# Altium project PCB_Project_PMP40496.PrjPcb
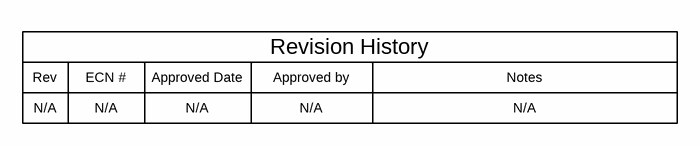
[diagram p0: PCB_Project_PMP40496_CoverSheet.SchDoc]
TID: N/A; TechSupport: http://www.ti.com/support; SCH_Rev: E1; PRJ_Title: 2-cell USB Boost Charger with OTG Reference Design; PRJ_Number: PMP40496; PRJ_Engineer: San Chen; PRJ_Customer: Public Release; PCB_Rev: E1; PCB_Layout: San Chen; CopyrightYear: 2018
4 sheets, 186 parts. Net scope: global (net labels, ports and power ports of the same name join across sheets).
Board file: PCB_Project_PMP40496_PCB.PcbDoc
Sheets:
  PCB_Project_PMP40496_CoverSheet.SchDoc
  PCB_Project_PMP40496_BatteryPack.SchDoc
  PCB_Project_PMP40496_BatteryCharge.SchDoc
  PCB_Project_PMP40496_Control.SchDoc

## Sheet PCB_Project_PMP40496_CoverSheet.SchDoc: Block Diagram
size 431 x 279 mm; Date: Not shown in title block; ApprovedBy: Not shown in title block; CheckedBy: Not shown in title block; Author: Not shown in title block; CompanyName: Not shown in title block; DrawnBy: San Chen; Engineer: Not shown in title block; Organization: Not shown in title block; Address1: Not shown in title block; Address2: Not shown in title block; Address3: Not shown in title block; Address4: Not shown in title block; DocumentNumber: 1; Revision: Use project parameter SCH_Rev; SheetNumber: 1; SheetTotal: 4; PageSetup: Record=PageOptions¦CenterHorizontal=True¦CenterVertical=True¦PrintScale=1.00¦XCorrection=1.00¦YCorrection=1.00¦PrintKind=0¦BorderSize=5000000¦LeftOffset=0¦BottomOffset=0¦Orientation=2¦PaperLength=1000¦PaperWidth=1000¦Scale=100¦PaperSource=15¦PrintQuality=600¦MediaType=1¦DitherType=10¦PaperKind=Letter¦PrintScaleMode=1

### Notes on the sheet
- Rev
- N/A
- ECN #
- Approved Date
- Approved by
- Revision History
- Notes

## Sheet PCB_Project_PMP40496_BatteryPack.SchDoc: Battery Pack
size 431 x 279 mm; Date: Not shown in title block; ApprovedBy: Not shown in title block; CheckedBy: Not shown in title block; Author: Not shown in title block; CompanyName: Not shown in title block; DrawnBy: San Chen; Engineer: Not shown in title block; Organization: Not shown in title block; Address1: Not shown in title block; Address2: Not shown in title block; Address3: Not shown in title block; Address4: Not shown in title block; DocumentNumber: 1; Revision: Use project parameter SCH_Rev; SheetNumber: 4; SheetTotal: 4; PageSetup: Record=PageOptions¦CenterHorizontal=True¦CenterVertical=True¦PrintScale=1.00¦XCorrection=1.00¦YCorrection=1.00¦PrintKind=0¦BorderSize=5000000¦LeftOffset=0¦BottomOffset=0¦Orientation=2¦PaperLength=1000¦PaperWidth=1000¦Scale=100¦PaperSource=15¦PrintQuality=600¦MediaType=1¦DitherType=10¦PaperKind=Letter¦PrintScaleMode=1
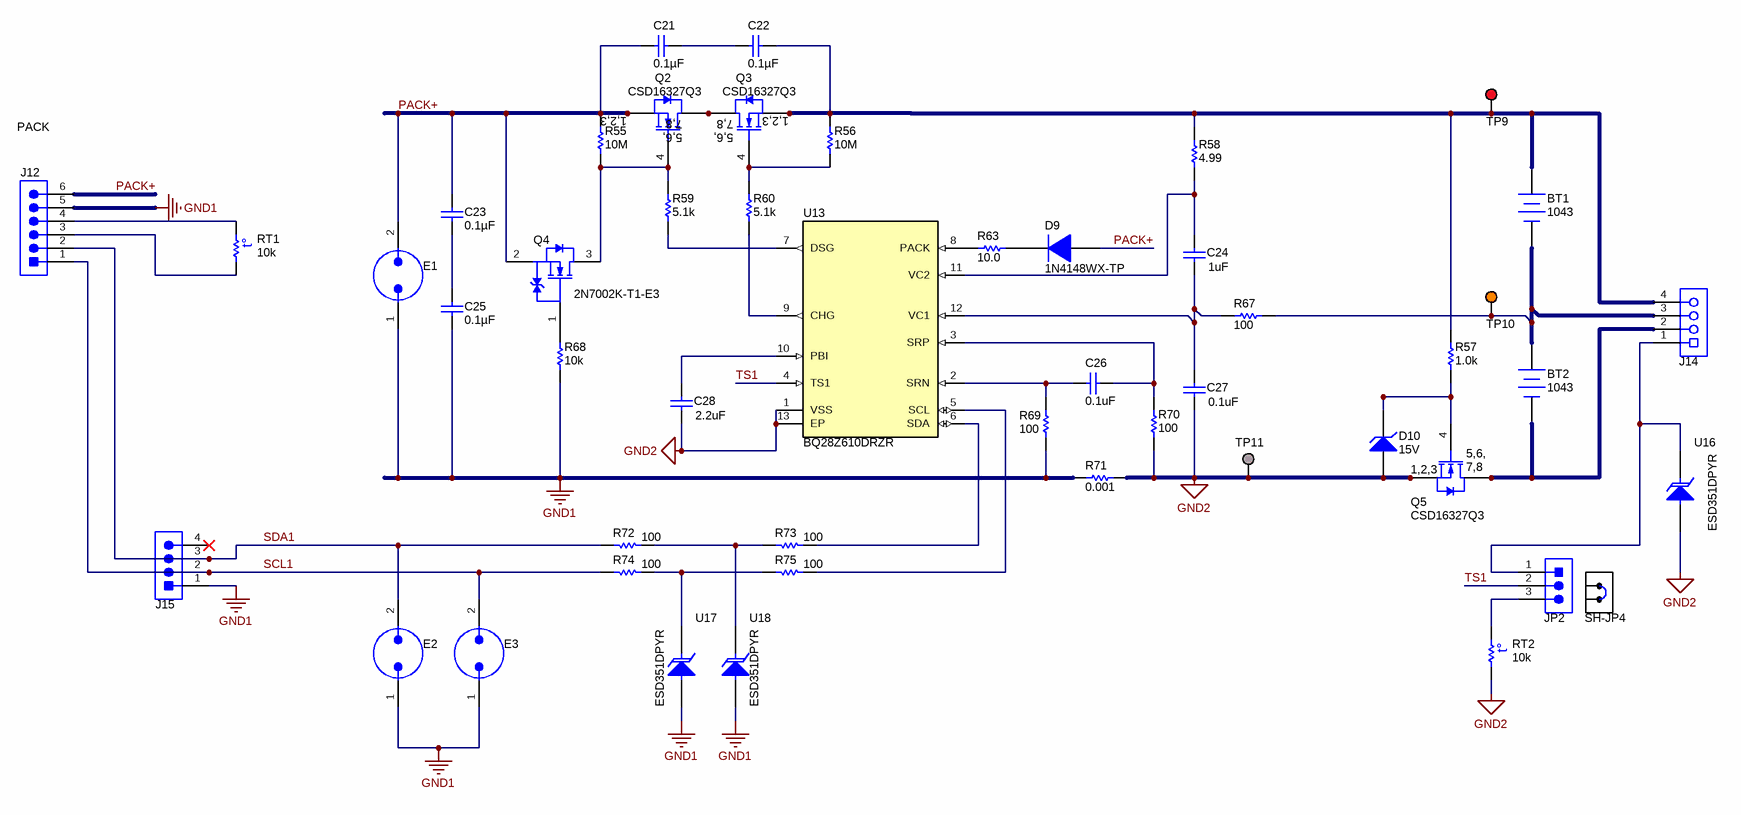
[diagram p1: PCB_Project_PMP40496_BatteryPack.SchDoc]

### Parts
BT1  1043  [BAT_1043]
BT2  1043  [BAT_1043]
C21  ValueDisplayed: 0.1µF  [0402]  (hidden comment: C1005X7R1H104K050BB)
C22  ValueDisplayed: 0.1µF  [0402]  (hidden comment: C1005X7R1H104K050BB)
C23  ValueDisplayed: 0.1µF  [0402]  (hidden comment: C1005X7R1H104K050BB)
C24  ValueDisplayed: 1uF  [0402]  (hidden comment: EMK105BJ105KVHF)
C25  ValueDisplayed: 0.1µF  [0402]  (hidden comment: C1005X7R1H104K050BB)
C26  ValueDisplayed: 0.1uF  [0402]  (hidden comment: GRM155R71E104KE14D)
C27  ValueDisplayed: 0.1uF  [0402]  (hidden comment: GRM155R71E104KE14D)
C28  ValueDisplayed: 2.2uF  [0402]  (hidden comment: GRM155R61C225KE11D)
D9  1N4148WX-TP  [SOD-323]
D10  value 15V  [SOD-323]  (hidden comment: MMSZ5245BS-7-F)
E1  N/A  [SPARK_GAP2]  (value not drawn)  (no BOM)
E2  N/A  [SPARK_GAP2]  (value not drawn)  (no BOM)
E3  N/A  [SPARK_GAP2]  (value not drawn)  (no BOM)
J12  395021006  [HEADER_395021006]  (value not drawn)
J14  ED555/4DS  [TERM_BLK_ED555-4DS]  (value not drawn)
J15  22/05/3041  [CONN_22-05-3041]  (value not drawn)
JP2  PEC03SAAN  [CONN_PEC03SAAN]  (value not drawn)
Q2  CSD16327Q3  [DQG0008A]
Q3  CSD16327Q3  [DQG0008A]
Q4  2N7002K-T1-E3  [SOT-23]
Q5  CSD16327Q3  [DQG0008A]
R55  ValueDisplayed: 10M  [0402]  (hidden comment: CRCW040210M0JNED)
R56  ValueDisplayed: 10M  [0402]  (hidden comment: CRCW040210M0JNED)
R57  ValueDisplayed: 1.0k  [0603]  (hidden comment: RC0603JR-071KL)
R58  ValueDisplayed: 4.99  [0402]  (hidden comment: CRCW04024R99FKED)
R59  ValueDisplayed: 5.1k  [0402]  (hidden comment: CRCW04025K10JNED)
R60  ValueDisplayed: 5.1k  [0402]  (hidden comment: CRCW04025K10JNED)
R63  ValueDisplayed: 10.0  [0402]  (hidden comment: MCR01MZPF10R0)
R67  ValueDisplayed: 100  [0603]  (hidden comment: CRCW0603100RFKEA)
R68  ValueDisplayed: 10k  [0402]  (hidden comment: ERJ-2GEJ103X)
R69  ValueDisplayed: 100  [0402]  (hidden comment: RC0402FR-07100RL)
R70  ValueDisplayed: 100  [0402]  (hidden comment: RC0402FR-07100RL)
R71  ValueDisplayed: 0.001  [WSLP1206-001]  (hidden comment: WSLP12061L000FEA)
R72  ValueDisplayed: 100  [0402]  (hidden comment: RC0402FR-07100RL)
R73  ValueDisplayed: 100  [0402]  (hidden comment: RC0402FR-07100RL)
R74  ValueDisplayed: 100  [0402]  (hidden comment: RC0402FR-07100RL)
R75  ValueDisplayed: 100  [0402]  (hidden comment: RC0402FR-07100RL)
RT1  value 10k  [0402S]  (hidden comment: NCP15XH103F03RC)
RT2  value 10k  [0402S]  (hidden comment: NCP15XH103F03RC)
SH-JP4  SNT-100-BK-G  [SNT-100-BK-G]  (value not drawn)
TP9  5010  [Keystone5010]  (value not drawn)
TP10  5013  [Keystone5013]  (value not drawn)
TP11  5019  [Keystone_5019]  (value not drawn)
U13  BQ28Z610DRZR  [DRZ0012A]
U16  ESD351DPYR  [DPY0002A]
U17  ESD351DPYR  [DPY0002A]
U18  ESD351DPYR  [DPY0002A]

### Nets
GND1: C25.2 E1.1 E2.1 E3.1 J12.5 J15.1 R68.1 R69.1 R71.1 U17.2(A) U18.2(A)
GND2: C27.2 C28.2 D10.2(A) Q5.1(S) Q5.2(S) Q5.3(S) R70.1 R71.2 RT2.1 TP11.1 U13.1(VSS) U13.13(EP) U16.2(A)
PACK+: C21.2 C23.1 D9.2(A) E1.2 J12.6 Q2.1(S) Q2.2(S) Q2.3(S) Q4.2(S) R55.2
SCL1: E3.2 J12.1 J15.2 R74.1
SDA1: E2.2 J12.2 J15.3 R72.1
TS1: JP2.2 U13.4(TS1)
NetBT1_1: BT1.1(+) C22.1 J14.4 Q3.1(S) Q3.2(S) Q3.3(S) R56.2 R57.2 R58.2 TP9.1
NetBT1_2: BT1.2(-) BT2.1(+) J14.3 R67.2 TP10.1
NetBT2_2: BT2.2(-) J14.2 Q5.5(D) Q5.6(D) Q5.7(D) Q5.8(D) Q5.9(D)
NetC21_1: C21.1 C22.2
NetC23_2: C23.2 C25.1
NetC24_1: C24.1 R58.1 U13.11(VC2)
NetC24_2: C24.2 C27.1 R67.1 U13.12(VC1)
NetC26_1: C26.1 R69.2 U13.2(SRN)
NetC26_2: C26.2 R70.2 U13.3(SRP)
NetC28_1: C28.1 U13.10(PBI)
NetD9_1: D9.1(K) R63.2
NetD10_1: D10.1(K) Q5.4(G) R57.1
NetJ12_3: J12.3 RT1.1
NetJ12_4: J12.4 RT1.2
NetJ14_1: J14.1 JP2.1 U16.1(K)
NetJP2_3: JP2.3 RT2.2
NetQ2_4: Q2.4(G) Q4.3(D) R55.1 R59.2
NetQ2_5: Q2.5(D) Q2.6(D) Q2.7(D) Q2.8(D) Q2.9(D) Q3.5(D) Q3.6(D) Q3.7(D) Q3.8(D) Q3.9(D)
NetQ3_4: Q3.4(G) R56.1 R60.2
NetQ4_1: Q4.1(G) R68.2
NetR59_1: R59.1 U13.7(DSG)
NetR60_1: R60.1 U13.9(CHG)
NetR63_1: R63.1 U13.8(PACK)
NetR72_2: R72.2 R73.1 U18.1(K)
NetR73_2: R73.2 U13.6(SDA)
NetR74_2: R74.2 R75.1 U17.1(K)
NetR75_2: R75.2 U13.5(SCL)

Not connected (* = marked no-connect by the designer): J15 4*

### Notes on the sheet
- PACK

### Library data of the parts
BT1 BT2 = CMP-0003634-1: Battery Holder, Plastic, 18650, TH; Manufacturer: Keystone
C21-C23 C25 = C1005X7R1H104K050BB: CAP, CERM, 0.1 µF, 50 V, +/- 10%, X7R, 0402; Manufacturer: TDK; Polarized: N; CompType: Capacitor; Value: 0.1uF; U/M: EA; Cap_F: 0.0000001; Tolerance_%: 10; ESR_ohm: 0.039064; Value1: 0.039064 ohm; VDC_V: 50; Value2: 50V; IRMS_A: 0.814669; TaMin_C: -55; TaMax_C: 125; SizeArea_mm2: 0.5; SizeAreaWB_mm2: 3; SizeX_mm: 1; SizeZ_mm: 0.6; AEC Category: Q200
C24 = CMP-0006347-2: CAP, CERM, 1 uF, 16 V, +/- 10%, X5R, 0402; Manufacturer: Taiyo Yuden; TaMin_C: -55°C; Polarized: N; SizeAreaWB_mm2: 3; Value1: Unknown; U/M: EA; Value: 1uF; TaMax_C: 85°C; SizeZ_mm: 0.6; SizeX_mm: 1; SizeY_mm: 0.5; Value2: 16V; CompType: Capacitor; Cap_F: 1µF; AEC Category: Q200
C26 C27 = CMP-0006659-2: CAP, CERM, 0.1 uF, 25 V, +/- 10%, X7R, 0402; Manufacturer: MuRata; TaMin_C: -55°C; Polarized: N; SizeAreaWB_mm2: 3; Value1: Unknown; U/M: EA; Value: 0.1uF; TaMax_C: 125°C; SizeZ_mm: 0.6; SizeX_mm: 1; SizeY_mm: 0.5; Value2: 25V; CompType: Capacitor; Cap_F: 100nF; AEC Category: Q200
C28 = CMP-0006594-2: CAP, CERM, 2.2 uF, 16 V, +/- 10%, X5R, 0402; Manufacturer: MuRata; TaMin_C: -55°C; Polarized: N; SizeAreaWB_mm2: 3; Value1: Unknown; U/M: EA; Value: 2.2uF; TaMax_C: 85°C; SizeZ_mm: 0.6; SizeX_mm: 1; SizeY_mm: 0.5; Value2: 16V; CompType: Capacitor; Cap_F: 2.2µF; AEC Category: Q200
D9 = CMP-0082069-2: Diode, Switching, 75 V, 0.15 A, SOD-323; Manufacturer: Micro Commercial Components; AEC Category: Q101; AEC Qualified: N; Value1: 0.15A; SizeX_mm: 2.7; Vr_V: 75V; Vf_V: 1V; SizeZ_mm: 1; SizeY_mm: 1.35; Value: 75V; SizeAreaWB_mm2: 8.695; TJmax_C: 150°C; RJC_CperW: 625; Io_A: 1.5dA; SizeArea_mm2: 3.645
D10 = CMP-0005833-4: Diode, Zener, 15 V, 200 mW, SOD-323; Manufacturer: Diodes Inc.; SizeY_mm: 1.35; RJA_CperW: 350; SizeX_mm: 2.7; AEC Category: Q101; SizeAreaWB_mm2: 8.695; SizeZ_mm: 1; Power_W: 200mW; SizeArea_mm2: 3.645; Value1: 0.2W
E1-E3 = SparkGap: Spark Gap; SymbolCreator: a0412235
J12 = CMP-0055336-1: Terminal Block Header, 3.5mm 6x1, Tin, R/A, TH; Manufacturer: Molex; CNHeader: FALSE; Green_Lifecycle: Active; Green_REACh: Passed; CT: TRUE
J14 = CMP-0074917-1: Terminal Block, 3.5mm Pitch, 4x1, TH; Manufacturer: On-Shore Technology; Cert_VDE: Y; CNHeader: False; Current_A: 6A; Green_Lifecycle: Not Set; Shrouded: N; Gender: Female; Green_REACh: Incomplete; Voltage_V: 150V; Row_Count: 1; Pitch_mm: 3.5; ContactFinish: Brass; CT: True
J15 = CMP-0055187-1: Header (friction lock), 100mil, 4x1, R/A, TH; Manufacturer: Molex; CNHeader: FALSE; Green_Lifecycle: Active; Green_REACh: Passed
JP2 = CMP-0002338-1: Header, 100mil, 3x1, Tin, TH; Manufacturer: Sullins Connector Solutions; CNHeader: TRUE; Current_A: 3A; Green_Lifecycle: Not Set; Shrouded: N; Gender: Male; Green_REACh: Incomplete; Voltage_V: 1.8kV; Row_Count: 1; Pitch_mm: 2.54; CT: FALSE; Cert_UL: Y
Q2 Q3 Q5 = CMP-0000257-1: MOSFET, N-CH, 25 V, 60 A, DQG0008A (VSON-CLIP-8); Alternate Manufacturer: None; Manufacturer: Texas Instruments; SizeZ_mm: 1.1; ChType: N; Value2: 6.2 nC; Value1: 0.004; VdsMax_V: 25V; SizeX_mm: 3.3; Vgs_V: 10V; Value: 25V; Rdson45_ohm: 4.8m; SizeArea_mm2: 10.89; AEC Category: Q101; IdsMax_A: 60A; SizeAreaWB_mm2: 18.49; U/M: EA; QgTyp_nC: 6.2
Q4 = CMP-0000773-1: MOSFET, N-CH, 60 V, 0.3 A, SOT-23; Alternate Manufacturer: None; Manufacturer: Vishay-Siliconix; SizeZ_mm: 1.1; ChType: N; Value2: 0.4 nC; VdsMax_V: 60V; SizeX_mm: 2.5; SizeY_mm: 3; Vgs_V: 20V; Value: 60V; Rdson45_ohm: 4; SizeArea_mm2: 7.5; AEC Category: Q101; IdsMax_A: 3dA; SizeAreaWB_mm2: 14; U/M: EA; QgTyp_nC: 0.4
R55 R56 = CMP-0026826-2: RES, 10 M, 5%, 0.063 W, AEC-Q200 Grade 0, 0402; Manufacturer: Vishay-Dale; Power_W: 63mW; TempCo: 200 ppm/C; Value_Code: 10M0; Value: 10Meg; EIA_Code: E24; SizeX_mm: 1; SizeY_mm: 0.5; SizeZ_mm: 0.6; Value2: 0.063W; AEC Qualified: Y; VDC_V: 50V; AEC Category: Q200; AEC Grade: 0
R57 = CMP-0025899-5: RES, 1.0 k, 5%, 0.1 W, 0603; Manufacturer: Yageo; Power_W: 100mW; TempCo: 100 ppm/C; Value_Code: 1k00; Value: 1.0k; EIA_Code: E24; Res_ohm: 1k; SizeX_mm: 1.6; SizeY_mm: 0.8; SizeZ_mm: 1; Value2: 0.1W; SizeArea_mm2: 1.28; AEC Qualified: N; VDC_V: 75V; AEC Category: Q200; SizeAreaWB_mm2: 4.68
R58 = CMP-0026434-2: RES, 4.99, 1%, 0.063 W, AEC-Q200 Grade 0, 0402; Manufacturer: Vishay-Dale; Power_W: 63mW; TempCo: 100 ppm/C; Value_Code: 4R99; Value: 4.99; EIA_Code: E96; SizeX_mm: 1; SizeY_mm: 0.5; SizeZ_mm: 0.6; Value2: 0.063W; AEC Qualified: Y; VDC_V: 50V; AEC Category: Q200; AEC Grade: 0
R59 R60 = CMP-0026951-5: RES, 5.1 k, 5%, 0.063 W, AEC-Q200 Grade 0, 0402; Manufacturer: Vishay-Dale; Power_W: 63mW; TempCo: 200 ppm/C; Value_Code: 5k10; Value: 5.1k; EIA_Code: E24; SizeX_mm: 1; SizeY_mm: 0.5; SizeZ_mm: 0.6; Value2: 0.063W; AEC Qualified: Y; VDC_V: 50V; AEC Category: Q200; AEC Grade: 0
R63 = CMP-0026717-1: RES, 10.0, 1%, 0.063 W, 0402; Manufacturer: Rohm; Power_W: 63mW; TempCo: 100 ppm/C; Value_Code: 10R0; U/M: EA; Value: 10.0; EIA_Code: E96; Res_ohm: 10; SizeX_mm: 1; SizeY_mm: 0.5; SizeZ_mm: 0.6; Value2: 0.063W; AEC Qualified: N; VDC_V: 50V; AEC Category: Q200
R67 = CMP-0021991-4: RES, 100, 1%, 0.1 W, AEC-Q200 Grade 0, 0603; Manufacturer: Vishay-Dale; Power_W: 100mW; TempCo: 100 ppm/C; Value_Code: 100R; Value: 100; EIA_Code: E96; SizeX_mm: 1.6; SizeY_mm: 0.8; SizeZ_mm: 1; Value2: 0.1W; SizeArea_mm2: 1.28; AEC Qualified: Y; VDC_V: 75V; AEC Category: Q200; AEC Grade: 0
R68 = CMP-0026994-4: RES, 10 k, 5%, 0.1 W, AEC-Q200 Grade 0, 0402; Manufacturer: Panasonic; Power_W: 100mW; TempCo: 200 ppm/C; Value_Code: 10k0; U/M: EA; Value: 10k; EIA_Code: E24; SizeX_mm: 1; SizeY_mm: 0.5; SizeZ_mm: 0.6; Value2: 0.1W; AEC Qualified: Y; VDC_V: 50V; AEC Grade: 0; AEC Category: Q200
R69 R70 R72-R75 = CMP-0026722-1: RES, 100, 1%, 0.063 W, 0402; Manufacturer: Yageo America; Power_W: 63mW; TempCo: 100 ppm/C; Value_Code: 100R; U/M: EA; Value: 100; EIA_Code: E96; SizeX_mm: 1; SizeY_mm: 0.5; SizeZ_mm: 0.6; Value2: 0.063W; AEC Qualified: N; VDC_V: 50V; AEC Category: Q200
R71 = CMP-0018569-2: RES, 0.001, 1%, 1 W, 1206; Manufacturer: Vishay-Dale; Power_W: 1W; TempCo: 275 ppm/C; Value_Code: 1L000; U/M: EA; Value: 0.001; EIA_Code: E96; Res_ohm: 1m; SizeX_mm: 3.2; SizeY_mm: 1.6; SizeZ_mm: 0.89; SizeArea_mm2: 5.12; AEC Qualified: N; AEC Category: Q200
RT1 RT2 = CMP-0002344-2: Thermistor NTC, 10.0k ohm, 1%, 0402; Manufacturer: MuRata; TaMax_C: 125°C; SizeX_mm: 1; SizeY_mm: 0.5; TaMin_C: -40°C; Power_W: 100mW; SizeZ_mm: 0.6; SizeAreaWB_mm2: 3; U/M: EA
SH-JP4 = CMP-0003623-3: Shunt, 100mil, Gold plated, Black; Alternate PartNumber: 969102-0000-DA; Manufacturer: Samtec; Alternate Manufacturer: 3M; Value: 1x2
TP9 = 5010: Test Point, Multipurpose, Red, TH; Manufacturer: Keystone; CompType: Test Point Loop; ContactFinish: Silver
TP10 = 5013: Test Point, Multipurpose, Orange, TH; Manufacturer: Keystone; CompType: Test Point Loop; ContactFinish: Silver
TP11 = CMP-0055162-1: Test Point, Miniature, SMT; Manufacturer: Keystone; CNHeader: FALSE; Green_Lifecycle: Active; Green_REACh: Passed; CT: TRUE
U13 = CMP-0076164-1: Battery Fuel Gauge with Integrated Protector for 1-2 Series Packs, DRZ0012A (VSON-12); Manufacturer: Texas Instruments; Alternate PartNumber: BQ28Z610DRZT; SizeAreaWB_mm2: 17.5; SizeArea_mm2: 10.0; SizeZ_mm: 1.0; Green_REACh: Passed; SizeY_mm: 2.5; Green_Lifecycle: Active; U/M: EA; CompType: IC; SizeX_mm: 4.0
U16-U18 = CMP-0084110-2: 1-Channel 30 kV ESD Protection Diode With Low Clamping Voltage in 0402 Package, DPY0002A (X1SON-2); Manufacturer: Texas Instruments; AEC Category: Q200; SizeX_mm: 1.0; SizeZ_mm: 0.45; CompType: IC; AEC Qualified: N; SizeY_mm: 0.6; SizeAreaWB_mm2: 3.2; Rating: Catalog

## Sheet PCB_Project_PMP40496_BatteryCharge.SchDoc: Boost Charger
size 431 x 279 mm; Date: Not shown in title block; ApprovedBy: Not shown in title block; CheckedBy: Not shown in title block; Author: Not shown in title block; CompanyName: Not shown in title block; DrawnBy: San Chen; Engineer: Not shown in title block; Organization: Not shown in title block; Address1: Not shown in title block; Address2: Not shown in title block; Address3: Not shown in title block; Address4: Not shown in title block; DocumentNumber: 1; Revision: Use project parameter SCH_Rev; SheetNumber: 2; SheetTotal: 4; PageSetup: Record=PageOptions¦CenterHorizontal=True¦CenterVertical=True¦PrintScale=1.00¦XCorrection=1.00¦YCorrection=1.00¦PrintKind=0¦BorderSize=5000000¦LeftOffset=0¦BottomOffset=0¦Orientation=2¦PaperLength=1000¦PaperWidth=1000¦Scale=100¦PaperSource=15¦PrintQuality=600¦MediaType=1¦DitherType=10¦PaperKind=Letter¦PrintScaleMode=1
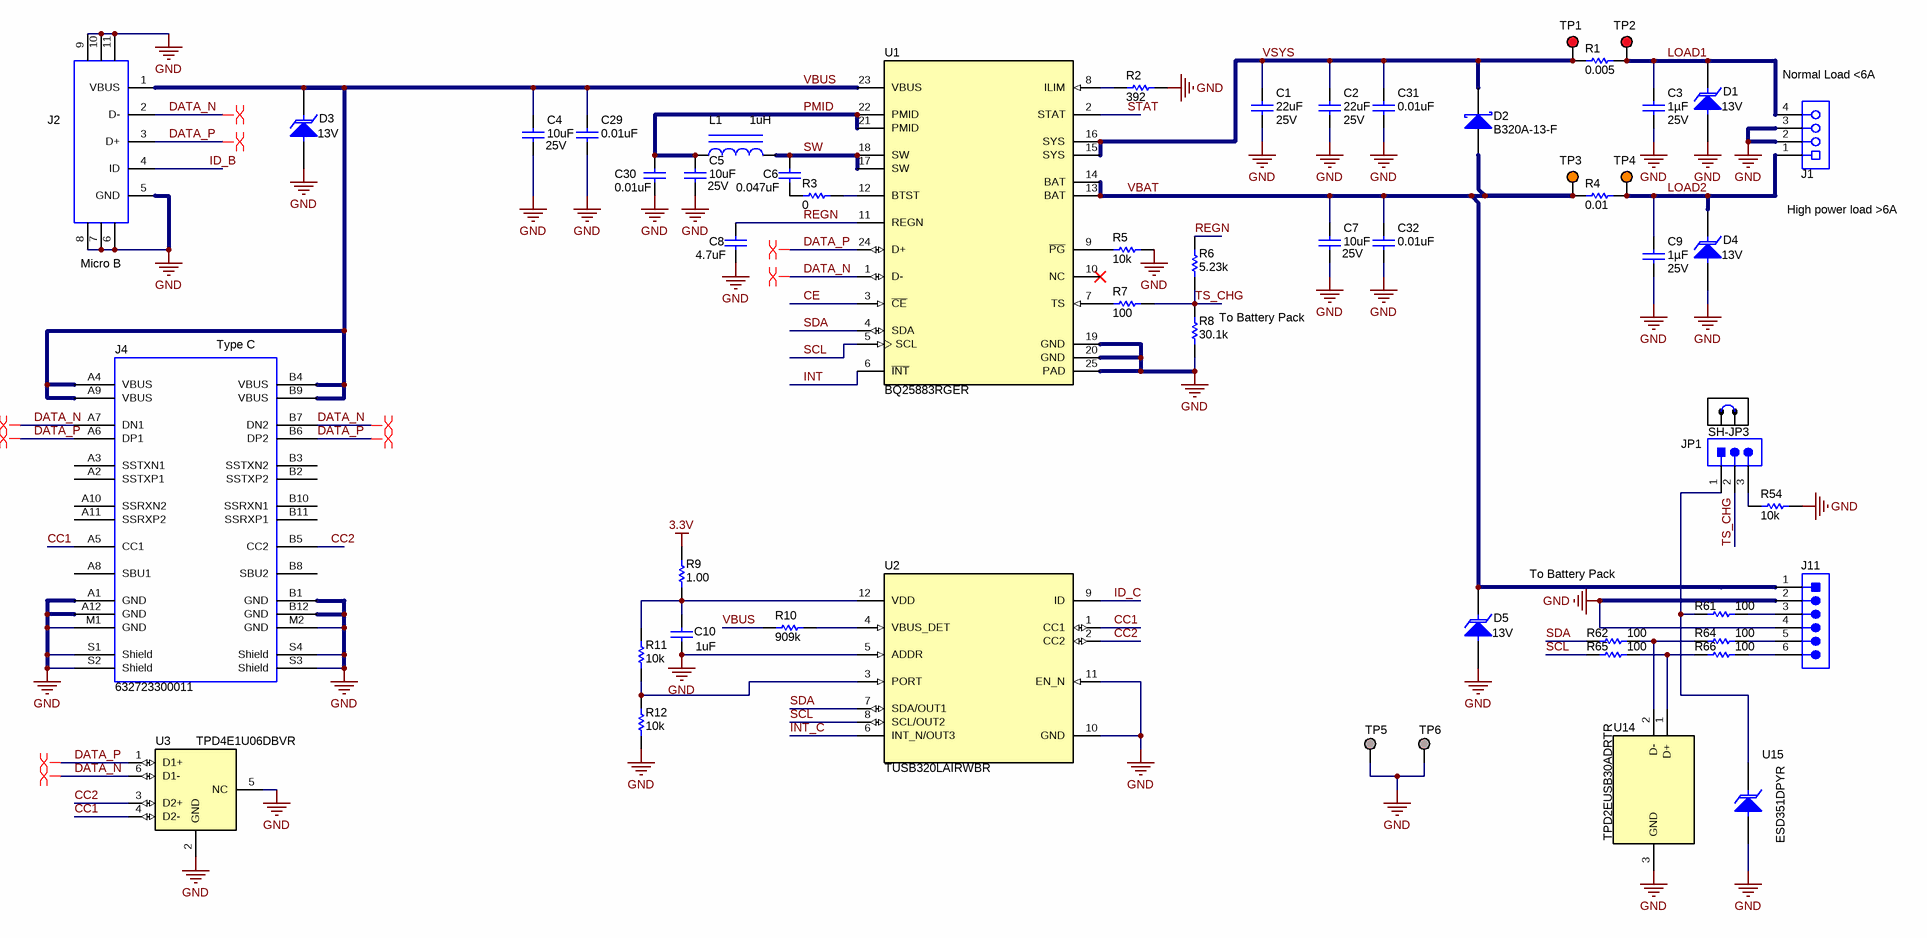
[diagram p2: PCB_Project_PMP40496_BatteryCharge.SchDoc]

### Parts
C1  VDC_V: 25V  ValueDisplayed: 22uF  [0805_HV]  (hidden comment: GRM21BR61E226ME44L)
C2  VDC_V: 25V  ValueDisplayed: 22uF  [0805_HV]  (hidden comment: GRM21BR61E226ME44L)
C3  VDC_V: 25V  ValueDisplayed: 1µF  [0603]  (hidden comment: CGJ3E1X7R1E105K080AC)
C4  VDC_V: 25V  ValueDisplayed: 10uF  [0603]  (hidden comment: C1608X5R1E106M080AC)
C5  VDC_V: 25V  ValueDisplayed: 10uF  [0603]  (hidden comment: C1608X5R1E106M080AC)
C6  ValueDisplayed: 0.047uF  [0402]  (hidden comment: GRM155R71E473KA88D)
C7  VDC_V: 25V  ValueDisplayed: 10uF  [0603]  (hidden comment: C1608X5R1E106M080AC)
C8  ValueDisplayed: 4.7uF  [0402_065]  (hidden comment: C1005X5R1A475K050BC)
C9  VDC_V: 25V  ValueDisplayed: 1µF  [0603]  (hidden comment: CGJ3E1X7R1E105K080AC)
C10  ValueDisplayed: 1uF  [0402]  (hidden comment: EMK105BJ105KVHF)
C29  ValueDisplayed: 0.01uF  [0402]  (hidden comment: GRM155R71E103KA01D)
C30  ValueDisplayed: 0.01uF  [0402]  (hidden comment: GRM155R71E103KA01D)
C31  ValueDisplayed: 0.01uF  [0402]  (hidden comment: GRM155R71E103KA01D)
C32  ValueDisplayed: 0.01uF  [0402]  (hidden comment: GRM155R71E103KA01D)
D1  value 13V  [SOD-123W]  (hidden comment: PTVS13VS1UR,115)
D2  B320A-13-F  [SMA]
D3  value 13V  [SOD-123W]  (hidden comment: PTVS13VS1UR,115)
D4  value 13V  [SOD-123W]  (hidden comment: PTVS13VS1UR,115)
D5  value 13V  [SOD-123W]  (hidden comment: PTVS13VS1UR,115)
J1  ED555/4DS  [TERM_BLK_ED555-4DS]  (value not drawn)
J2  1051640001  [Molex_1051640001]  (value not drawn)
J4  632723300011  [Wurth_632_723_300_011]
J11  395021006  [HEADER_395021006]  (value not drawn)
JP1  PEC03SAAN  [CONN_PEC03SAAN]  (value not drawn)
L1  ValueDisplayed: 1uH  [WE-MAPI_3020]  (hidden comment: 74438336100)
R1  ValueDisplayed: 0.005  [1206]  (hidden comment: CSR1206-0R005F1)
R2  ValueDisplayed: 392  [0402]  (hidden comment: CRCW0402392RFKED)
R3  ValueDisplayed: 0  [0402]  (hidden comment: CRCW04020000Z0ED)
R4  ValueDisplayed: 0.01  [1206]  (hidden comment: CSR1206FK10L0)
R5  ValueDisplayed: 10k  [0402]  (hidden comment: ERJ-2GEJ103X)
R6  ValueDisplayed: 5.23k  [0402]  (hidden comment: CRCW04025K23FKED)
R7  ValueDisplayed: 100  [0402]  (hidden comment: RC0402FR-07100RL)
R8  ValueDisplayed: 30.1k  [0402]  (hidden comment: RC0402FR-0730K1L)
R9  ValueDisplayed: 1.00  [0402]  (hidden comment: CRCW04021R00FKED)
R10  ValueDisplayed: 909k  [0402]  (hidden comment: CRCW0402909KFKED)
R11  ValueDisplayed: 10k  [0402]  (hidden comment: ERJ-2GEJ103X)
R12  ValueDisplayed: 10k  [0402]  (hidden comment: ERJ-2GEJ103X)
R54  ValueDisplayed: 10k  [0402]  (hidden comment: ERJ-2GEJ103X)
R61  ValueDisplayed: 100  [0402]  (hidden comment: RC0402FR-07100RL)
R62  ValueDisplayed: 100  [0402]  (hidden comment: RC0402FR-07100RL)
R64  ValueDisplayed: 100  [0402]  (hidden comment: RC0402FR-07100RL)
R65  ValueDisplayed: 100  [0402]  (hidden comment: RC0402FR-07100RL)
R66  ValueDisplayed: 100  [0402]  (hidden comment: RC0402FR-07100RL)
SH-JP3  SNT-100-BK-G  [SNT-100-BK-G]  (value not drawn)
TP1  5010  [Keystone5010]  (value not drawn)
TP2  5010  [Keystone5010]  (value not drawn)
TP3  5013  [Keystone5013]  (value not drawn)
TP4  5013  [Keystone5013]  (value not drawn)
TP5  5019  [Keystone_5019]  (value not drawn)
TP6  5019  [Keystone_5019]  (value not drawn)
U1  BQ25883RGER  [RGE0024H]
U2  TUSB320LAIRWBR  [RWB0012A]
U3  TPD4E1U06DBVR  [DBV0006A_N]
U14  TPD2EUSB30ADRTR  [DRT0003A]
U15  ESD351DPYR  [DPY0002A]

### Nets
3.3V: R9.2
GND: C1.2 C2.2 C3.2 C4.2 C5.2 C7.2 C8.2 C9.2 C10.2 C29.2 C30.2 C31.2 C32.2 D1.2(A) D3.2(A) D4.2(A) D5.2(A) J1.2 J1.3 J2.5(GND) J2.6 J2.7 J2.8 J2.9 J2.10 J2.11 J4.A1(GND) J4.A12(GND) J4.B1(GND) J4.B12(GND) J4.M1(GND) J4.M2(GND) J4.S1(Shield) J4.S2(Shield) J4.S3(Shield) J4.S4(Shield) J11.2 J11.4 R2.1 R5.1 R8.1 R12.2 R54.1 TP5.1 TP6.1 U1.19(GND) U1.20(GND) U1.25(PAD) U2.5(ADDR) U2.10(GND) U2.11(EN_N) U3.2(GND) U3.5(NC) U14.3(GND) U15.2(A)
CC1: J4.A5(CC1) U2.1(CC1) U3.4(D2-)
CC2: J4.B5(CC2) U2.2(CC2) U3.3(D2+)
CE: U1.3(~{CE})
DATA_N: J2.2(D-) J4.A7(DN1) J4.B7(DN2) U1.1(D-) U3.6(D1-)
DATA_P: J2.3(D+) J4.A6(DP1) J4.B6(DP2) U1.24(D+) U3.1(D1+)
ID_B: J2.4(ID)
ID_C: U2.9(ID)
INT: U1.6(~{INT})
INT_C: U2.6(INT_N/OUT3)
LOAD1: C3.1 D1.1(K) J1.4 R1.2 TP2.1
LOAD2: C9.1 D4.1(K) J1.1 R4.1 TP4.1
PMID: C5.1 C30.1 L1.1 U1.21(PMID) U1.22(PMID)
REGN: C8.1 R6.2 U1.11(REGN)
SCL: R65.2 U1.5(SCL) U2.8(SCL/OUT2)
SDA: R62.2 U1.4(SDA) U2.7(SDA/OUT1)
STAT: U1.2(STAT)
SW: C6.2 L1.2 U1.17(SW) U1.18(SW)
TS_CHG: JP1.2 R6.1 R7.1 R8.2
VBAT: C7.1 C32.1 D2.2(A) D5.1(K) J11.1 R4.2 TP3.1 U1.13(BAT) U1.14(BAT)
VBUS: C4.1 C29.1 D3.1(K) J2.1(VBUS) J4.A4(VBUS) J4.A9(VBUS) J4.B4(VBUS) J4.B9(VBUS) R10.1 U1.23(VBUS)
VSYS: C1.1 C2.1 C31.1 D2.1(K) R1.1 TP1.1 U1.15(SYS) U1.16(SYS)
NetC6_1: C6.1 R3.1
NetC10_1: C10.1 R9.1 R11.1 U2.12(VDD)
NetJ11_3: J11.3 R61.1
NetJ11_5: J11.5 R64.1
NetJ11_6: J11.6 R66.1
NetJP1_1: JP1.1 R61.2 U15.1(K)
NetJP1_3: JP1.3 R54.2
NetR2_2: R2.2 U1.8(ILIM)
NetR3_2: R3.2 U1.12(BTST)
NetR5_2: R5.2 U1.9(~{PG})
NetR7_2: R7.2 U1.7(TS)
NetR10_2: R10.2 U2.4(VBUS_DET)
NetR11_2: R11.2 R12.1 U2.3(PORT)
NetR62_1: R62.1 R64.2 U14.2(D-)
NetR65_1: R65.1 R66.2 U14.1(D+)

Not connected (* = marked no-connect by the designer): J4 A2(SSTXP1) A3(SSTXN1) A8(SBU1) A10(SSRXN2) A11(SSRXP2) B2(SSTXP2) B3(SSTXN2) B8(SBU2) B10(SSRXN1) B11(SSRXP1); U1 10(NC)*

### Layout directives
differential pair: DATA_N, DATA_P

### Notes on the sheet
- (near J1) Normal Load <6A
- (near J1) High power load >6A
- (near J2) Micro B
- (near J4) Type C
- (near R8) To Battery Pack
- To Battery Pack

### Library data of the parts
C1 C2 = CMP-0008305-2: CAP, CERM, 22 uF, 25 V, +/- 20%, X5R, 0805; Manufacturer: MuRata; TaMin_C: -55°C; Polarized: N; SizeAreaWB_mm2: 6.75; Value1: Unknown; U/M: EA; Value: 22uF; TaMax_C: 85°C; SizeZ_mm: 1.45; SizeX_mm: 2; SizeY_mm: 1.25; Cap_Case: 0805; SizeArea_mm2: 2.5; CompType: Capacitor; Cap_F: 22µF; AEC Category: Q200
C3 C9 = CMP-0083856-1: CAP, CERM, 1 µF, 25 V,+/- 10%, X7R, 0603; Manufacturer: TDK; TaMin_C: -55°C; Polarized: N; SizeAreaWB_mm2: 4.68; U/M: EA; Value: 1uF; TaMax_C: 125°C; SizeZ_mm: 1; SizeX_mm: 1.6; SizeY_mm: 0.8; SizeArea_mm2: 1.28; AEC Category: Q200
C4 C5 = CMP-0007007-5: CAP, CERM, 10 uF, 25 V, +/- 20%, X5R, 0603; Manufacturer: TDK; TaMin_C: -55°C; ESR_ohm: 4.639m; Polarized: N; SizeAreaWB_mm2: 4.68; Value1: 0.004639 ohm; U/M: EA; Value: 10uF; TaMax_C: 85°C; SizeZ_mm: 1; SizeX_mm: 1.6; SizeY_mm: 0.8; SizeArea_mm2: 1.28; CompType: Capacitor; Cap_F: 10µF; IRMS_A: 2.41407A; AEC Category: Q200
C6 = CMP-0006669-2: CAP, CERM, 0.047 uF, 25 V, +/- 10%, X7R, 0402; Manufacturer: MuRata; TaMin_C: -55°C; Polarized: N; SizeAreaWB_mm2: 3; Value1: Unknown; U/M: EA; TaMax_C: 125°C; SizeZ_mm: 0.6; SizeX_mm: 1; SizeY_mm: 0.5; Value2: 25V; CompType: Capacitor; Cap_F: 47nF; AEC Category: Q200
C7 = CMP-0007007-5: CAP, CERM, 10 uF, 25 V, +/- 20%, X5R, 0603; Manufacturer: TDK; TaMin_C: -55°C; ESR_ohm: 4.639m; Polarized: N; SizeAreaWB_mm2: 4.68; Value1: 0.004639 ohm; U/M: EA; Value: 10uF; TaMax_C: 85°C; SizeZ_mm: 1; SizeX_mm: 1.6; SizeY_mm: 0.8; SizeArea_mm2: 1.28; Cap_F: 10µF; IRMS_A: 2.41407A; AEC Category: Q200
C8 = CMP-0006268-2: CAP, CERM, 4.7 uF, 10 V, +/- 10%, X5R, 0402; Manufacturer: TDK; TaMin_C: -55°C; ESR_ohm: 3.417m; Polarized: N; SizeAreaWB_mm2: 3; Value1: 0.003417 ohm; U/M: EA; Value: 4.7uF; TaMax_C: 85°C; SizeZ_mm: 0.65; SizeX_mm: 1; SizeY_mm: 0.5; Value2: 10V; CompType: Capacitor; Cap_F: 4.7µF; IRMS_A: 2.7063A; AEC Category: Q200
C10 = CMP-0006347-2: as C24 on sheet PCB_Project_PMP40496_BatteryPack
C29-C32 = CMP-0006658-2: CAP, CERM, 0.01 uF, 25 V, +/- 10%, X7R, 0402; Manufacturer: MuRata; TaMin_C: -55°C; Polarized: N; SizeAreaWB_mm2: 3; Value1: Unknown; U/M: EA; Value: 0.01uF; TaMax_C: 125°C; SizeZ_mm: 0.6; SizeX_mm: 1; SizeY_mm: 0.5; Value2: 25V; CompType: Capacitor; Cap_F: 10nF; AEC Category: Q200
D1 D3-D5 = CMP-0005819-4: Diode, TVS, Uni, 13 V, 21.5 Vc, SOD-123W; Manufacturer: NXP Semiconductor; SizeAreaWB_mm2: 12.15; SizeZ_mm: 1; RJA_CperW: 220; SizeX_mm: 3.5; Ipp: 18.6A; Vc: 21.5V; SizeY_mm: 1.7; Vbr_Min: 14.4V; Vbr_Max: 15.15V; SizeArea_mm2: 5.95; AEC Category: Q101
D2 = CMP-0028347-2: Diode, Schottky, 20 V, 3 A, SMA; Manufacturer: Diodes Inc.; Green_Lifecycle: Active; SizeX_mm: 5.59; Io_A: 3A; TJmax_C: 125°C; SizeAreaWB_mm2: 37.3428; Green_REACh: Passed; SizeY_mm: 2.92; SizeArea_mm2: 16.3228; RJC_CperW: 25; AEC Category: Q101; SizeZ_mm: 2.87; Value2: 0.5V; Vf_V: 5dV; Vr_V: 20V; Value: 20V
J1 = CMP-0074917-1: as J14 on sheet PCB_Project_PMP40496_BatteryPack
J2 = CMP-0055311-1: Receptacle, USB 2.0, Micro B, 5 Position, R/A, SMT; Manufacturer: Molex; CNHeader: FALSE; Current_A: 1.8A; Gender: Female; Voltage_V: 30V; Pitch_mm: 0.65; ContactFinish: Gold; CT: TRUE; Cert_UL: Y
J4 = CMP-0080891-1: Connector, Receptacle, USB Type C, R/A; Manufacturer: Wurth Elektronik; Current_A: 3A; Gender: Female; Voltage_V: 5V; ContactFinish: Gold; Cert_UL: Y
J11 = CMP-0055336-1: as J12 on sheet PCB_Project_PMP40496_BatteryPack
JP1 = CMP-0002338-1: as JP2 on sheet PCB_Project_PMP40496_BatteryPack
L1 = CMP-0064157-1: Inductor, Shielded, 1 uH, 4 A, 0.032 ohm, SMD; Manufacturer: Wurth Electronics; PartNumber: 74438336010; Material: Composite,Ferrite,Metal; Tolerance_%: 20%; Current Rating: 4A; Saturation Current: 5A; DCR_Ohm: 32mR; Self Resonant Frequency: 67MHz; Test Frequency: 100kHz
R1 = CMP-0078497-1: RES, 0.005, 1%, 1 W, 1206; Manufacturer: Riedon; Power_W: 1W; TempCo: 50 ppm/C; Value_Code: 5L000; Value: 0.005; EIA_Code: E96; Res_ohm: 5m; SizeX_mm: 3.2; SizeY_mm: 1.6; SizeZ_mm: 1.35; SizeArea_mm2: 5.12; AEC Qualified: N; AEC Category: Q200
R2 = CMP-0026326-2: RES, 392, 1%, 0.063 W, AEC-Q200 Grade 0, 0402; Manufacturer: Vishay-Dale; Power_W: 63mW; TempCo: 100 ppm/C; Value_Code: 392R; Value: 392; EIA_Code: E96; SizeX_mm: 1; SizeY_mm: 0.5; SizeZ_mm: 0.6; Value2: 0.063W; AEC Qualified: Y; VDC_V: 50V; AEC Category: Q200; AEC Grade: 0
R3 = CMP-0026822-3: RES, 0, 5%, 0.063 W, AEC-Q200 Grade 0, 0402; Manufacturer: Vishay-Dale; Power_W: 63mW; TempCo: 200 ppm/C; Value_Code: 0000; Value: 0; EIA_Code: E24; SizeX_mm: 1; SizeY_mm: 0.5; SizeZ_mm: 0.6; Value2: 0.063W; AEC Qualified: Y; VDC_V: 50V; AEC Category: Q200
R4 = CMP-0017256-2: RES, 0.01, 1%, 0.5 W, 1206; Manufacturer: Stackpole Electronics Inc; Power_W: 500mW; TempCo: 100 ppm/C; Value_Code: R010; U/M: EA; Value: 0.01; EIA_Code: E96; SizeX_mm: 3.2; SizeY_mm: 1.6; SizeZ_mm: 1.35; Value2: 0.5W; SizeArea_mm2: 5.12; AEC Category: Q200
R5 R11 R12 R54 = CMP-0026994-4: as R68 on sheet PCB_Project_PMP40496_BatteryPack
R6 = CMP-0026464-2: RES, 5.23 k, 1%, 0.063 W, AEC-Q200 Grade 0, 0402; Manufacturer: Vishay-Dale; Power_W: 63mW; TempCo: 100 ppm/C; Value_Code: 5k23; Value: 5.23k; EIA_Code: E96; SizeX_mm: 1; SizeY_mm: 0.5; SizeZ_mm: 0.6; Value2: 0.063W; AEC Qualified: Y; VDC_V: 50V; AEC Category: Q200; AEC Grade: 0
R7 R61 R62 R64-R66 = CMP-0026722-1: as R69 on sheet PCB_Project_PMP40496_BatteryPack
R8 = CMP-0026730-1: RES, 30.1 k, 1%, 0.063 W, 0402; Manufacturer: Yageo America; Power_W: 63mW; TempCo: 100 ppm/C; Value_Code: 30k1; U/M: EA; Value: 30.1k; EIA_Code: E96; SizeX_mm: 1; SizeY_mm: 0.5; SizeZ_mm: 0.6; Value2: 0.063W; AEC Qualified: N; VDC_V: 50V; AEC Category: Q200
R9 = CRCW04021R00FKED: RES, 1.00, 1%, 0.063 W, 0402; Manufacturer: Vishay-Dale; CompType: Resistor; Value: 1.00; Res_ohm: 1; Value_Code: 1R00; Power_W: 0.063; Value2: 0.063W; VDC_V: 50; TempCo: 100 ppm/C; SizeArea_mm2: 0.5; SizeZ_mm: 0.6; EIA_Code: E96; U/M: EA; AEC Category: Q200
R10 = CMP-0026603-2: RES, 909 k, 1%, 0.063 W, AEC-Q200 Grade 0, 0402; Manufacturer: Vishay-Dale; Power_W: 63mW; TempCo: 100 ppm/C; Value: 909k; EIA_Code: E96; SizeX_mm: 1; SizeY_mm: 0.5; SizeZ_mm: 0.6; Value2: 0.063W; AEC Qualified: Y; VDC_V: 50V; AEC Category: Q200; AEC Grade: 0
SH-JP3 = CMP-0003623-3: as SH-JP4 on sheet PCB_Project_PMP40496_BatteryPack
TP1 TP2 = 5010: as TP9 on sheet PCB_Project_PMP40496_BatteryPack
TP3 TP4 = 5013: as TP10 on sheet PCB_Project_PMP40496_BatteryPack
TP5 TP6 = CMP-0055162-1: as TP11 on sheet PCB_Project_PMP40496_BatteryPack
U1 = CMP-0086115-1: I2C Controlled, 2-Cell, 2A Boost-Mode Battery Charger for USB Input, RGE0024H (VQFN-24); Manufacturer: Texas Instruments; AEC Category: Q200; SizeY_mm: 4; AEC Qualified: N; CompType: IC; SizeAreaWB_mm2: 25; SizeArea_mm2: 16; SizeZ_mm: 1
U2 = CMP-0073635-2: USB Type-C Configuration Channel Logic and Port Control, RWB0012A (X2QFN-12); Alternate Manufacturer: Texas Instruments; SizeAreaWB_mm2: 6.76; SizeZ_mm: 0.4; SizeX_mm: 1.6; SizeArea_mm2: 2.56; CompType: IC; AEC Category: Q200; AEC Qualified: N; Rating: Catalog
U3 = CMP-0066605-1: Quad-Channel High-Speed ESD Protection Device, DBV0006A (SOT-23-6); Alternate Manufacturer: Texas Instruments; SizeAreaWB_mm2: 14.82; U/M: EA; SizeZ_mm: 1.45; SizeX_mm: 2.8; SizeY_mm: 2.9; SizeArea_mm2: 8.12; CompType: IC
U14 = CMP-0043103-2: ESD / Surge Solution for High Speed, Low Voltage Interface, 2 Channels, -40 to +85 degC, 3-pin SOT (DRT), Green (RoHS & no Sb/Br); Manufacturer: Texas Instruments; IO Leakage Current(nA): 10; HDMI: TRUE; IO Capacitance(Typ)(pF): 0.7; SubFamily: ESD Solution; Breakdown Voltage(Min)(V): 4.5; Differential Capacitance(pF): 0.05; IEC 61000-4-2 Air-Gap(+/- kV): 8
U15 = CMP-0084110-2: as U16 on sheet PCB_Project_PMP40496_BatteryPack

## Sheet PCB_Project_PMP40496_Control.SchDoc: System Control
size 431 x 279 mm; Date: Not shown in title block; ApprovedBy: Not shown in title block; CheckedBy: Not shown in title block; Author: Not shown in title block; CompanyName: Not shown in title block; DrawnBy: San Chen; Engineer: Not shown in title block; Organization: Not shown in title block; Address1: Not shown in title block; Address2: Not shown in title block; Address3: Not shown in title block; Address4: Not shown in title block; DocumentNumber: 1; Revision: Use project parameter SCH_Rev; SheetNumber: 3; SheetTotal: 4; PageSetup: Record=PageOptions¦CenterHorizontal=True¦CenterVertical=True¦PrintScale=1.00¦XCorrection=1.00¦YCorrection=1.00¦PrintKind=0¦BorderSize=5000000¦LeftOffset=0¦BottomOffset=0¦Orientation=2¦PaperLength=1000¦PaperWidth=1000¦Scale=100¦PaperSource=15¦PrintQuality=600¦MediaType=1¦DitherType=10¦PaperKind=Letter¦PrintScaleMode=1
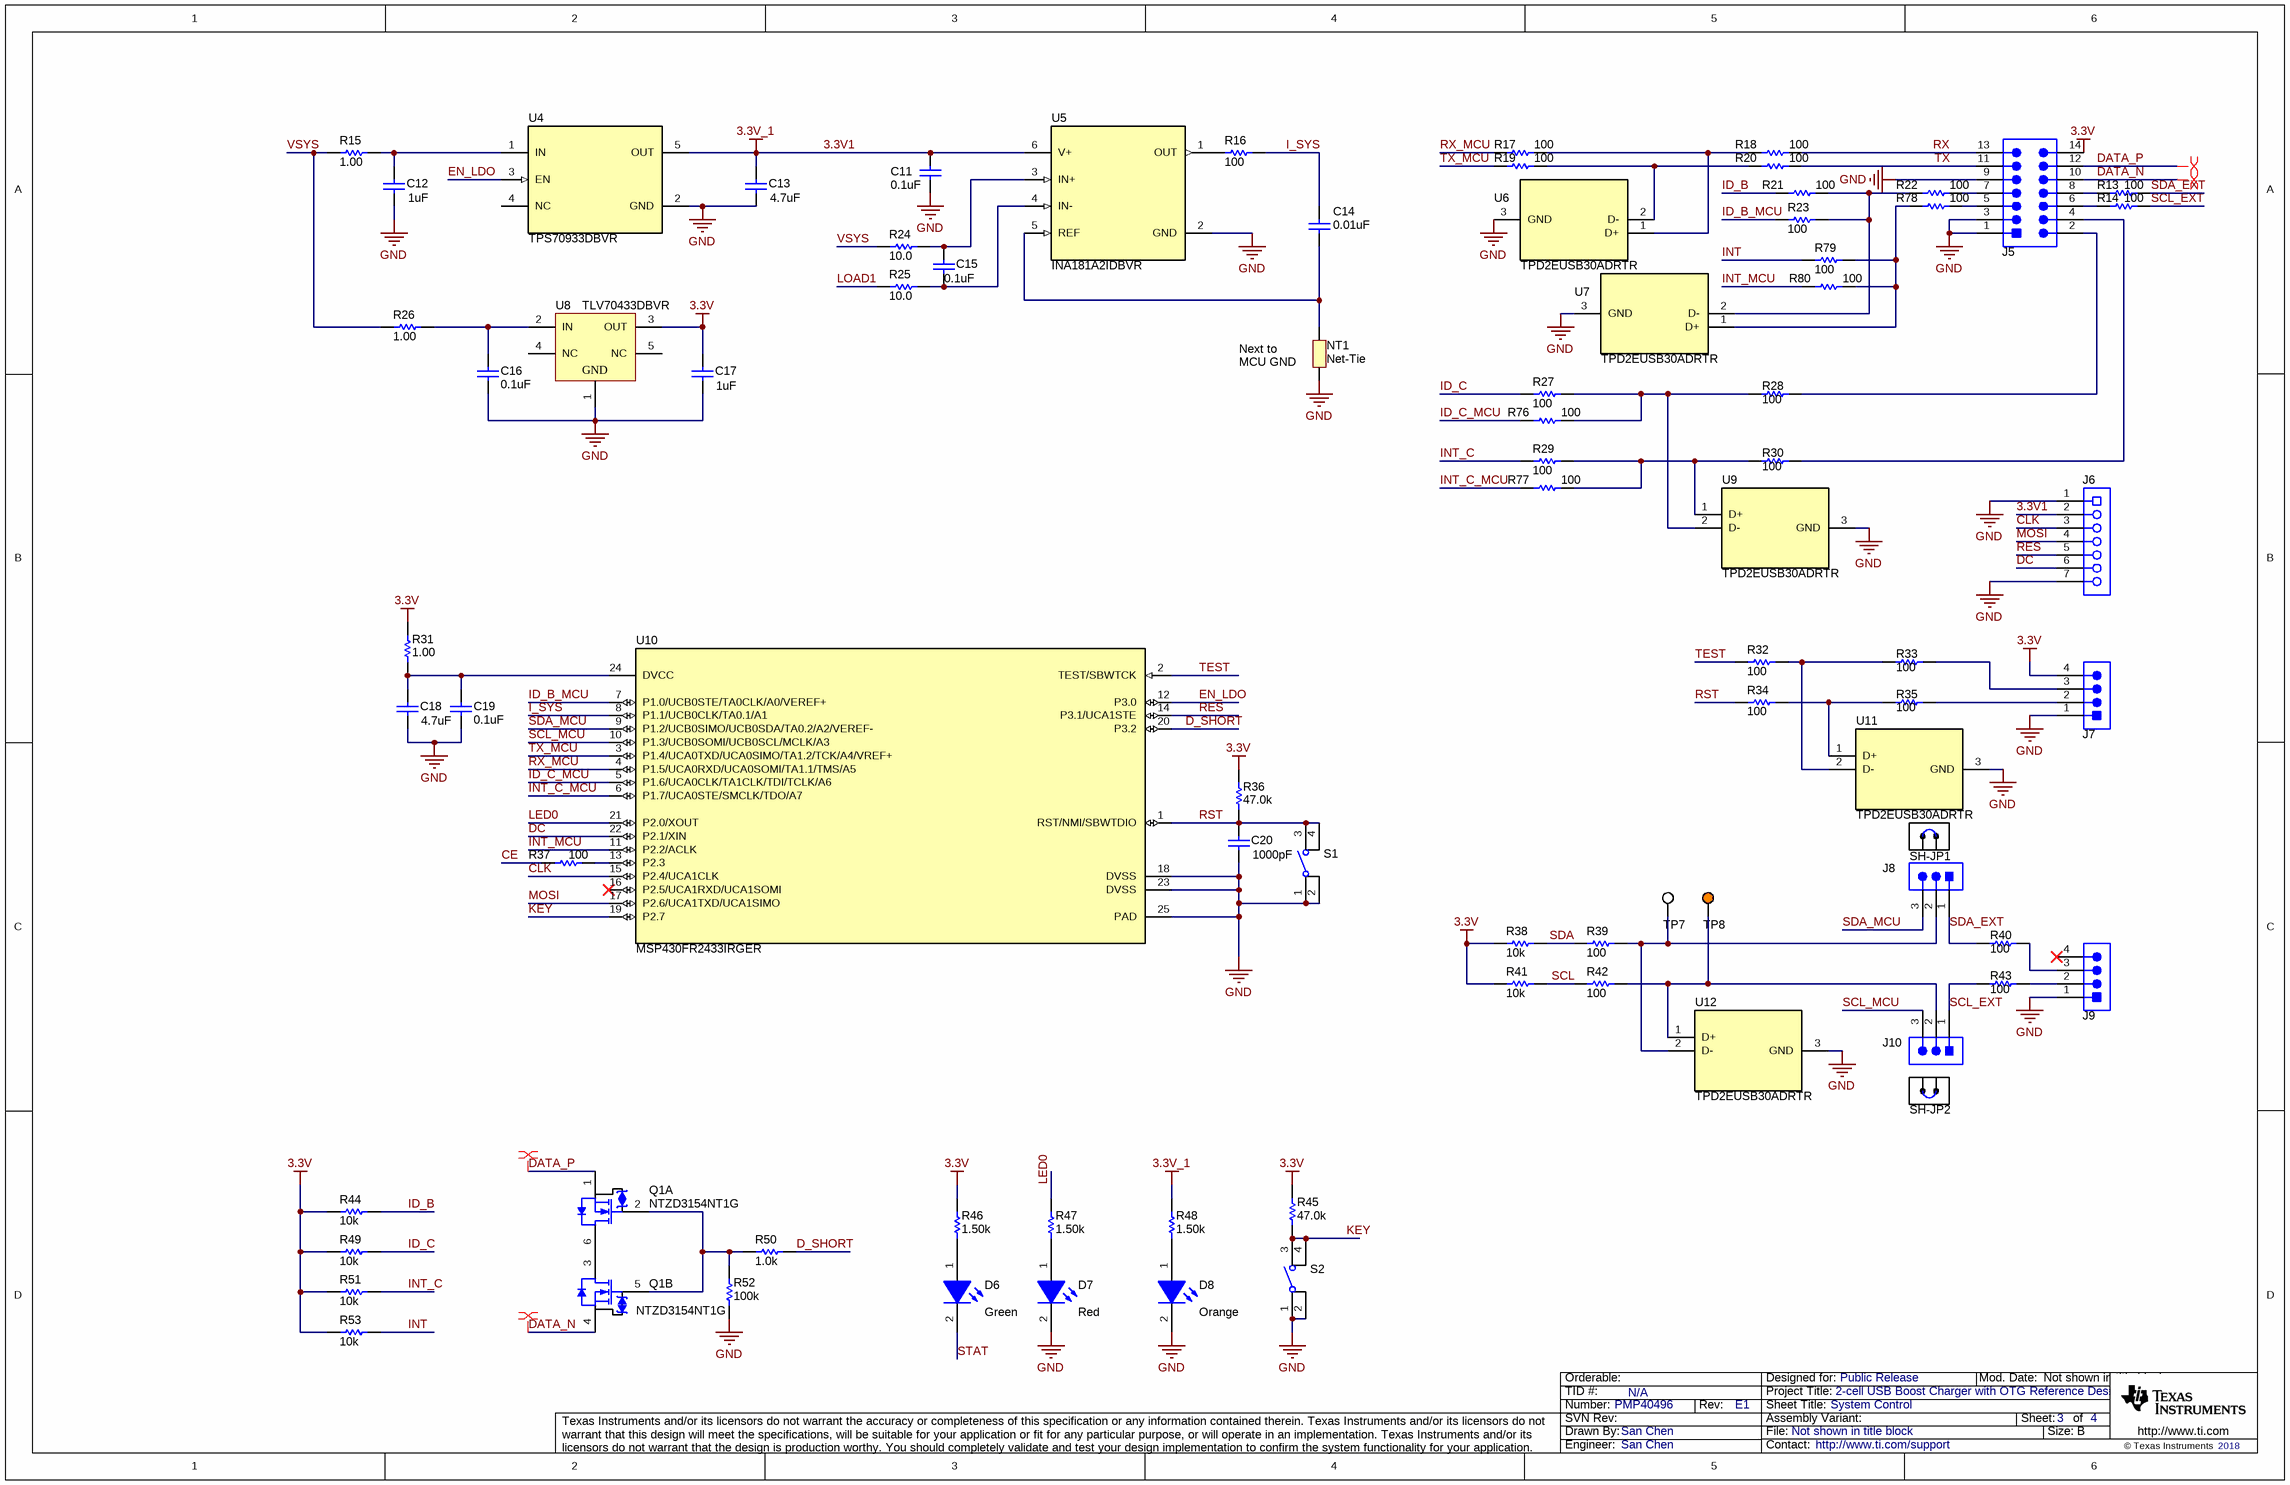
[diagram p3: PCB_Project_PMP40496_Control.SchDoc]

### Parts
C11  ValueDisplayed: 0.1uF  [0402]  (hidden comment: GRM155R71E104KE14D)
C12  ValueDisplayed: 1uF  [0402]  (hidden comment: EMK105BJ105KVHF)
C13  ValueDisplayed: 4.7uF  [0402_065]  (hidden comment: C1005X5R1A475K050BC)
C14  ValueDisplayed: 0.01uF  [0402]  (hidden comment: GRM155R71E103KA01D)
C15  ValueDisplayed: 0.1uF  [0402]  (hidden comment: GRM155R71E104KE14D)
C16  ValueDisplayed: 0.1uF  [0402]  (hidden comment: GRM155R71E104KE14D)
C17  ValueDisplayed: 1uF  [0402]  (hidden comment: EMK105BJ105KVHF)
C18  ValueDisplayed: 4.7uF  [0402_065]  (hidden comment: C1005X5R1A475K050BC)
C19  ValueDisplayed: 0.1uF  [0402]  (hidden comment: GRM155R71E104KE14D)
C20  ValueDisplayed: 1000pF  [0402]  (hidden comment: GRM155R61E102KA01D)
D6  value Green  [LED_LTST-C190]  (hidden comment: LTST-C190GKT)
D7  value Red  [LED_LTST-C190_Red]  (hidden comment: LTST-C190CKT)
D8  value Orange  [LED_LTST-C190]  (hidden comment: LTST-C190KFKT)
J5  PEC07DAAN  [CONN_PEC07DAAN]  (value not drawn)
J6  PPPC071LFBN-RC  [Sullins_xPxC071LFBN]  (value not drawn)
J7  22284043  [Molex_0022284043]  (value not drawn)
J8  PEC03SAAN  [CONN_PEC03SAAN]  (value not drawn)
J9  22/05/3041  [CONN_22-05-3041]  (value not drawn)
J10  PEC03SAAN  [CONN_PEC03SAAN]  (value not drawn)
NT1  Net-Tie  [Net-Tie_10mil]  (net tie, no BOM)
Q1  NTZD3154NT1G  [SOT-563]  (parts A,B of 2)
R13  ValueDisplayed: 100  [0402]  (hidden comment: RC0402FR-07100RL)
R14  ValueDisplayed: 100  [0402]  (hidden comment: RC0402FR-07100RL)
R15  ValueDisplayed: 1.00  [0402]  (hidden comment: CRCW04021R00FKED)
R16  ValueDisplayed: 100  [0402]  (hidden comment: RC0402FR-07100RL)
R17  ValueDisplayed: 100  [0402]  (hidden comment: RC0402FR-07100RL)
R18  ValueDisplayed: 100  [0402]  (hidden comment: RC0402FR-07100RL)
R19  ValueDisplayed: 100  [0402]  (hidden comment: RC0402FR-07100RL)
R20  ValueDisplayed: 100  [0402]  (hidden comment: RC0402FR-07100RL)
R21  ValueDisplayed: 100  [0402]  (hidden comment: RC0402FR-07100RL)
R22  ValueDisplayed: 100  [0402]  (hidden comment: RC0402FR-07100RL)
R23  ValueDisplayed: 100  [0402]  (hidden comment: RC0402FR-07100RL)
R24  ValueDisplayed: 10.0  [0402]  (hidden comment: MCR01MZPF10R0)
R25  ValueDisplayed: 10.0  [0402]  (hidden comment: MCR01MZPF10R0)
R26  ValueDisplayed: 1.00  [0402]  (hidden comment: CRCW04021R00FKED)
R27  ValueDisplayed: 100  [0402]  (hidden comment: RC0402FR-07100RL)
R28  ValueDisplayed: 100  [0402]  (hidden comment: RC0402FR-07100RL)
R29  ValueDisplayed: 100  [0402]  (hidden comment: RC0402FR-07100RL)
R30  ValueDisplayed: 100  [0402]  (hidden comment: RC0402FR-07100RL)
R31  ValueDisplayed: 1.00  [0402]  (hidden comment: CRCW04021R00FKED)
R32  ValueDisplayed: 100  [0402]  (hidden comment: RC0402FR-07100RL)
R33  ValueDisplayed: 100  [0402]  (hidden comment: RC0402FR-07100RL)
R34  ValueDisplayed: 100  [0402]  (hidden comment: RC0402FR-07100RL)
R35  ValueDisplayed: 100  [0402]  (hidden comment: RC0402FR-07100RL)
R36  ValueDisplayed: 47.0k  [0402]  (hidden comment: RC0402FR-0747KL)
R37  ValueDisplayed: 100  [0402]  (hidden comment: RC0402FR-07100RL)
R38  ValueDisplayed: 10k  [0402]  (hidden comment: ERJ-2GEJ103X)
R39  ValueDisplayed: 100  [0402]  (hidden comment: RC0402FR-07100RL)
R40  ValueDisplayed: 100  [0402]  (hidden comment: RC0402FR-07100RL)
R41  ValueDisplayed: 10k  [0402]  (hidden comment: ERJ-2GEJ103X)
R42  ValueDisplayed: 100  [0402]  (hidden comment: RC0402FR-07100RL)
R43  ValueDisplayed: 100  [0402]  (hidden comment: RC0402FR-07100RL)
R44  ValueDisplayed: 10k  [0402]  (hidden comment: ERJ-2GEJ103X)
R45  ValueDisplayed: 47.0k  [0402]  (hidden comment: RC0402FR-0747KL)
R46  ValueDisplayed: 1.50k  [0402]  (hidden comment: ERJ-2RKF1501X)
R47  ValueDisplayed: 1.50k  [0402]  (hidden comment: ERJ-2RKF1501X)
R48  ValueDisplayed: 1.50k  [0402]  (hidden comment: ERJ-2RKF1501X)
R49  ValueDisplayed: 10k  [0402]  (hidden comment: ERJ-2GEJ103X)
R50  ValueDisplayed: 1.0k  [0402]  (hidden comment: CRCW04021K00JNED)
R51  ValueDisplayed: 10k  [0402]  (hidden comment: ERJ-2GEJ103X)
R52  ValueDisplayed: 100k  [0402]  (hidden comment: CRCW0402100KJNED)
R53  ValueDisplayed: 10k  [0402]  (hidden comment: ERJ-2GEJ103X)
R76  ValueDisplayed: 100  [0402]  (hidden comment: RC0402FR-07100RL)
R77  ValueDisplayed: 100  [0402]  (hidden comment: RC0402FR-07100RL)
R78  ValueDisplayed: 100  [0402]  (hidden comment: RC0402FR-07100RL)
R79  ValueDisplayed: 100  [0402]  (hidden comment: RC0402FR-07100RL)
R80  ValueDisplayed: 100  [0402]  (hidden comment: RC0402FR-07100RL)
S1  B3SL-1002P  [SW_B3SL-1002P]  (value not drawn)
S2  B3SL-1002P  [SW_B3SL-1002P]  (value not drawn)
SH-JP1  SNT-100-BK-G  [SNT-100-BK-G]  (value not drawn)
SH-JP2  SNT-100-BK-G  [SNT-100-BK-G]  (value not drawn)
TP7  5007  [Keystone5007]  (value not drawn)
TP8  5008  [Keystone5008]  (value not drawn)
U4  TPS70933DBVR  [DBV0005A_N]
U5  INA181A2IDBVR  [DBV0006A_N]
U6  TPD2EUSB30ADRTR  [DRT0003A]
U7  TPD2EUSB30ADRTR  [DRT0003A]
U8  TLV70433DBVR  [DBV0005A_N]
U9  TPD2EUSB30ADRTR  [DRT0003A]
U10  MSP430FR2433IRGER  [RGE0024H_NV]
U11  TPD2EUSB30ADRTR  [DRT0003A]
U12  TPD2EUSB30ADRTR  [DRT0003A]

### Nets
3.3V: C17.1 J5.14 J7.4 R31.2 R36.2 R38.2 R41.2 R44.2 R45.2 R46.2 R49.2 R51.2 R53.2 U8.3(OUT)
3.3V1: C11.1 C13.1 J6.2 R48.2 U4.5(OUT) U5.6(V+)  [also labelled 3.3V_1]
GND: C11.2 C12.2 C13.2 C16.2 C17.2 C18.2 C19.2 C20.2 D7.2(K) D8.2(K) J5.1 J5.3 J5.9 J6.1 J6.7 J7.1 J9.1 NT1.1 R52.1 S1.1 S1.2 S2.1 S2.2 U4.2(GND) U5.2(GND) U6.3(GND) U7.3(GND) U8.1(GND) U9.3(GND) U10.18(DVSS) U10.23(DVSS) U10.25(PAD) U11.3(GND) U12.3(GND)
CE: R37.2
CLK: J6.3 U10.15(P2.4/UCA1CLK)
D_SHORT: R50.2 U10.20(P3.2)
DATA_N: J5.10 Q1.4(S)
DATA_P: J5.12 Q1.1(S)
DC: J6.6 U10.22(P2.1/XIN)
EN_LDO: U4.3(EN) U10.12(P3.0)
I_SYS: C14.1 R16.1 U10.8(P1.1/UCB0CLK/TA0.1/A1)
ID_B: R21.2 R44.1
ID_B_MCU: R23.2 U10.7(P1.0/UCB0STE/TA0CLK/A0/VEREF+)
ID_C: R27.2 R49.1
ID_C_MCU: R76.2 U10.5(P1.6/UCA0CLK/TA1CLK/TDI/TCLK/A6)
INT: R53.1 R79.2
INT_C: R29.2 R51.1
INT_C_MCU: R77.2 U10.6(P1.7/UCA0STE/SMCLK/TDO/A7)
INT_MCU: R80.2 U10.11(P2.2/ACLK)
KEY: R45.1 S2.3 S2.4 U10.19(P2.7)
LED0: R47.2 U10.21(P2.0/XOUT)
LOAD1: R25.1
MOSI: J6.4 U10.17(P2.6/UCA1TXD/UCA1SIMO)
RES: J6.5 U10.14(P3.1/UCA1STE)
RST: C20.1 R34.2 R36.1 S1.3 S1.4 U10.1(RST/NMI/SBWTDIO)
RX: J5.13 R18.1
RX_MCU: R17.2 U10.4(P1.5/UCA0RXD/UCA0SOMI/TA1.1/TMS/A5)
SCL: R41.1 R42.2
SCL_EXT: J10.1 R14.2 R43.2
SCL_MCU: J10.3 U10.10(P1.3/UCB0SOMI/UCB0SCL/MCLK/A3)
SDA: R38.1 R39.2
SDA_EXT: J8.1 R13.1 R40.2
SDA_MCU: J8.3 U10.9(P1.2/UCB0SIMO/UCB0SDA/TA0.2/A2/VEREF-)
STAT: D6.2(K)
TEST: R32.2 U10.2(TEST/SBWTCK)
TX: J5.11 R20.1
TX_MCU: R19.2 U10.3(P1.4/UCA0TXD/UCA0SIMO/TA1.2/TCK/A4/VREF+)
VSYS: R15.1 R24.1 R26.1
NetC12_1: C12.1 R15.2 U4.1(IN)
NetC14_2: C14.2 NT1.2 U5.5(REF)
NetC15_1: C15.1 R24.2 U5.3(IN+)
NetC15_2: C15.2 R25.2 U5.4(IN-)
NetC16_1: C16.1 R26.2 U8.2(IN)
NetC18_1: C18.1 C19.1 R31.1 U10.24(DVCC)
NetD6_1: D6.1(A) R46.1
NetD7_1: D7.1(A) R47.1
NetD8_1: D8.1(A) R48.1
NetJ5_2: J5.2 R28.1
NetJ5_4: J5.4 R30.1
NetJ5_5: J5.5 R78.1
NetJ5_6: J5.6 R14.1
NetJ5_7: J5.7 R22.1
NetJ5_8: J5.8 R13.2
NetJ7_2: J7.2 R35.1
NetJ7_3: J7.3 R33.1
NetJ8_2: J8.2 R39.1 TP7.1 U12.2(D-)
NetJ9_2: J9.2 R43.1
NetJ9_3: J9.3 R40.1
NetJ10_2: J10.2 R42.1 TP8.1 U12.1(D+)
NetQ1_2: Q1.2(G) Q1.5(G) R50.1 R52.2
NetQ1_3: Q1.3(D) Q1.6(D)
NetR16_2: R16.2 U5.1(OUT)
NetR17_1: R17.1 R18.2 U6.1(D+)
NetR19_1: R19.1 R20.2 U6.2(D-)
NetR21_1: R21.1 R22.2 R23.1 U7.2(D-)
NetR27_1: R27.1 R28.2 R76.1 U9.2(D-)
NetR29_1: R29.1 R30.2 R77.1 U9.1(D+)
NetR32_1: R32.1 R33.2 U11.2(D-)
NetR34_1: R34.1 R35.2 U11.1(D+)
NetR37_1: R37.1 U10.13(P2.3)
NetR78_2: R78.2 R79.1 R80.1 U7.1(D+)

Not connected (* = marked no-connect by the designer): J9 4*; U4 4(NC); U8 4(NC) 5(NC); U10 16(P2.5/UCA1RXD/UCA1SOMI)*

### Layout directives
differential pair: DATA_N, DATA_P

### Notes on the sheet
- (near NT1) Next to MCU GND

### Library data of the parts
C11 C15 C16 C19 = CMP-0006659-2: as C26 on sheet PCB_Project_PMP40496_BatteryPack
C12 C17 = CMP-0006347-2: as C24 on sheet PCB_Project_PMP40496_BatteryPack
C13 C18 = CMP-0006268-2: as C8 on sheet PCB_Project_PMP40496_BatteryCharge
C14 = CMP-0006658-2: as C29 on sheet PCB_Project_PMP40496_BatteryCharge
C20 = CMP-0006606-2: CAP, CERM, 1000 pF, 25 V, +/- 10%, X5R, 0402; Manufacturer: MuRata; TaMin_C: -55°C; Polarized: N; SizeAreaWB_mm2: 3; Value1: Unknown; U/M: EA; Value: 1000pF; TaMax_C: 85°C; SizeZ_mm: 0.6; SizeX_mm: 1; SizeY_mm: 0.5; Value2: 25V; CompType: Capacitor; Cap_F: 1nF; AEC Category: Q200
D6 = CMP-0002827-3: LED, Green, SMD; Manufacturer: Lite-On; Power_TotalModule: 100mW; Value2: 2.1V; Io_A: 20mA; Value1: 0.1W
D7 = CMP-0002842-2: LED, Red, SMD; Manufacturer: Lite-On; Power_TotalModule: 62.5mW; Value1: 0.0625W; Io_A: 20mA; Value2: 2V; Tjmax_C: 85°C
D8 = CMP-0002826-2: LED, Orange, SMD; Manufacturer: Lite-On; Io_A: 20mA; Power_TotalModule: 75mW; Value1: 0.075W; U/M: EA; Vf_V: 2V; Type: AlInGaP
J5 = CMP-0002339-2: Header, 100mil, 7x2, Tin, TH; Manufacturer: Sullins Connector Solutions; Current_A: 3A; Green_Lifecycle: Active; Shrouded: N; Gender: Male; Green_REACh: Passed; Voltage_V: 1.8kV; Row_Count: 2; RowSpacing_mm: 2.54; Cert_UL: Y
J6 = CMP-0054674-1: Receptacle, 2.54mm, 7x1, Gold, TH; Manufacturer: Sullins Connector Solutions; CNHeader: FALSE; Current_A: 3A; Gender: Female; Voltage_V: 250V; CompType: Socket Strip; Row_Count: 1; Pitch_mm: 2.54; ContactFinish: Tin; CT: TRUE; Cert_UL: Y
J7 = CMP-0055331-1: Header, 2.54mm, 4x1, Tin, TH; Manufacturer: Molex; CNHeader: TRUE; Current_A: 4A; Shrouded: N; Gender: Male; Voltage_V: 250V; Row_Count: 1; Pitch_mm: 2.54; CT: FALSE; Cert_UL: Y
J8 J10 = CMP-0002338-1: as JP2 on sheet PCB_Project_PMP40496_BatteryPack
J9 = CMP-0055187-1: as J15 on sheet PCB_Project_PMP40496_BatteryPack
NT1 = Net-Tie: Single point connection between nets.; SymbolCreator: codlsc
Q1 = CMP-0000223-1: MOSFET, 2-CH, N-CH, 20 V, 0.54 A, SOT-563; Alternate Manufacturer: None; Manufacturer: ON Semiconductor; SizeZ_mm: 0.6; ChType: N; Value2: 1.5 nC; Value1: 0; VdsMax_V: 20V; SizeX_mm: 1.6; Vgs_V: 6V; Value: 20V; Rdson45_ohm: 4d; SizeArea_mm2: 2.56; AEC Category: Q101; IdsMax_A: 5.4dA; SizeAreaWB_mm2: 6.76; U/M: EA; QgTyp_nC: 1.5
R13 R14 R16-R23 R27-R30 R32-R35 R37 R39 R40 R42 R43 R76-R80 = CMP-0026722-1: as R69 on sheet PCB_Project_PMP40496_BatteryPack
R15 R26 R31 = CRCW04021R00FKED: as R9 on sheet PCB_Project_PMP40496_BatteryCharge
R24 R25 = CMP-0026717-1: as R63 on sheet PCB_Project_PMP40496_BatteryPack
R36 R45 = CMP-0026737-1: RES, 47.0 k, 1%, 0.0625 W, 0402; Manufacturer: Yageo America; Power_W: 62.5mW; TempCo: 100 ppm/C; Value_Code: 47k0; U/M: EA; Value: 47.0k; Res_ohm: 47k; SizeX_mm: 1; SizeY_mm: 0.5; SizeZ_mm: 0.6; AEC Qualified: N; VDC_V: 50V; AEC Category: Q200
R38 R41 R44 R49 R51 R53 = CMP-0026994-4: as R68 on sheet PCB_Project_PMP40496_BatteryPack
R46-R48 = CMP-0026668-1: RES, 1.50 k, 1%, 0.1 W, AEC-Q200 Grade 0, 0402; Manufacturer: Panasonic; Power_W: 100mW; TempCo: 100 ppm/C; Value_Code: 1k50; U/M: EA; Value: 1.50k; EIA_Code: E96; Res_ohm: 1.5k; SizeX_mm: 1; SizeY_mm: 0.5; SizeZ_mm: 0.6; Value2: 0.1W; AEC Qualified: Y; VDC_V: 50V; AEC Grade: 0; AEC Category: Q200
R50 = CMP-0026852-3: RES, 1.0 k, 5%, 0.063 W, AEC-Q200 Grade 0, 0402; Manufacturer: Vishay-Dale; Power_W: 63mW; TempCo: 200 ppm/C; Value_Code: 1k00; Value: 1.0k; EIA_Code: E24; Res_ohm: 1k; SizeX_mm: 1; SizeY_mm: 0.5; SizeZ_mm: 0.6; Value2: 0.063W; AEC Qualified: Y; VDC_V: 50V; AEC Category: Q200; AEC Grade: 0
R52 = CMP-0026823-3: RES, 100 k, 5%, 0.063 W, AEC-Q200 Grade 0, 0402; Manufacturer: Vishay-Dale; Power_W: 63mW; TempCo: 200 ppm/C; Value: 100k; EIA_Code: E24; SizeX_mm: 1; SizeY_mm: 0.5; SizeZ_mm: 0.6; Value2: 0.063W; AEC Qualified: Y; VDC_V: 50V; AEC Category: Q200; AEC Grade: 0
S1 S2 = CMP-0002310-1: SWITCH TACTILE SPST-NO 0.05A 12V; Manufacturer: Omron Electronic Components; CurrentRating_mA: 50A; PositionCount: 1; SizeX_mm: 6.2; SizeY_mm: 6.5; SizeZ_mm: 3.4; SizeArea_mm2: 40.3; SizeAreaWB_mm2: 69.7; SwitchFunction: Off-Mom
SH-JP1 SH-JP2 = CMP-0003623-3: as SH-JP4 on sheet PCB_Project_PMP40496_BatteryPack
TP7 = 5007: Test Point, Compact, White, TH; Manufacturer: Keystone; CompType: Test Point Loop; ContactFinish: Silver
TP8 = 5008: Test Point, Compact, Orange, TH; Manufacturer: Keystone; CompType: Test Point Loop; ContactFinish: Silver
U4 = CMP-0073793-1: 150-mA, 30-V, Ultra-Low IQ, Wide Input Low-Dropout Regulator with Reverse Current Protection, DBV0005A (SOT-23-5); Alternate PartNumber: TPS70933DBVT; Alternate Manufacturer: Texas Instruments; Green_Lifecycle: Active; SizeAreaWB_mm2: 14.82; Green_REACh: Passed; U/M: EA; SizeZ_mm: 1.45; SizeX_mm: 2.8; SizeY_mm: 2.9; SizeArea_mm2: 8.12; CompType: IC
U5 = CMP-0013232-2: Bidirectional, Low- and High-Side Measurement, Multichannel, Voltage Output, Current-Sense Amplifier, DBV0006A (SOT-6); Manufacturer: Texas Instruments; SizeX_mm: 2.8; SizeY_mm: 2.9; CompType: IC; SizeZ_mm: 1.45; SizeArea_mm2: 8.12; SizeAreaWB_mm2: 14.82; U/M: EA
U6 U7 U9 U11 U12 = CMP-0043103-2: as U14 on sheet PCB_Project_PMP40496_BatteryCharge
U8 = CMP-0035588-1: Single Output LDO, 150 mA, Fixed 3.3 V Output, 2.5 to 24 V Input, with Ultra-Low IQ, 5-pin SOT-23 (DBV), -40 to 125 degC, Green (RoHS & no Sb/Br); Manufacturer: Texas Instruments; Accuracy(%): 2; Vout Adj(Min)(V): 3.3; Vin(Min)(V): 2.5; Vin(Max)(V): 24; SubFamily: Single Channel LDO; Iout(Max)(A): 0.15; Vdo(Typ)(mV): 400; Iq(Typ)(mA): 0.003
U10 = CMP-0076607-2: MSP430FR2433 16 MHz Ultra-Low-Power Microcontroller with 16 KB FRAM, 4 KB RAM, 19 IO, 4 Timers, RGE0024H (VQFN-24); Manufacturer: Texas Instruments; Alternate PartNumber: MSP430FR2433IRGET; SizeX_mm: 4.0; CompType: IC; SizeZ_mm: 1.0; SizeArea_mm2: 16.0; SizeAreaWB_mm2: 25.0; U/M: EA

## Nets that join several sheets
3.3V: PCB_Project_PMP40496_BatteryCharge (R9.2), PCB_Project_PMP40496_Control (14 pins)
GND: PCB_Project_PMP40496_BatteryCharge (55 pins), PCB_Project_PMP40496_Control (34 pins)
CE: PCB_Project_PMP40496_BatteryCharge (U1.3), PCB_Project_PMP40496_Control (R37.2)
DATA_N: PCB_Project_PMP40496_BatteryCharge (5 pins), PCB_Project_PMP40496_Control (J5.10 Q1.4)
DATA_P: PCB_Project_PMP40496_BatteryCharge (5 pins), PCB_Project_PMP40496_Control (J5.12 Q1.1)
ID_B: PCB_Project_PMP40496_BatteryCharge (J2.4), PCB_Project_PMP40496_Control (R21.2 R44.1)
ID_C: PCB_Project_PMP40496_BatteryCharge (U2.9), PCB_Project_PMP40496_Control (R27.2 R49.1)
INT: PCB_Project_PMP40496_BatteryCharge (U1.6), PCB_Project_PMP40496_Control (R53.1 R79.2)
INT_C: PCB_Project_PMP40496_BatteryCharge (U2.6), PCB_Project_PMP40496_Control (R29.2 R51.1)
LOAD1: PCB_Project_PMP40496_BatteryCharge (5 pins), PCB_Project_PMP40496_Control (R25.1)
SCL: PCB_Project_PMP40496_BatteryCharge (R65.2 U1.5 U2.8), PCB_Project_PMP40496_Control (R41.1 R42.2)
SDA: PCB_Project_PMP40496_BatteryCharge (R62.2 U1.4 U2.7), PCB_Project_PMP40496_Control (R38.1 R39.2)
STAT: PCB_Project_PMP40496_BatteryCharge (U1.2), PCB_Project_PMP40496_Control (D6.2)
VSYS: PCB_Project_PMP40496_BatteryCharge (8 pins), PCB_Project_PMP40496_Control (R15.1 R24.1 R26.1)

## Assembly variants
001: not fitted FID1 FID2 FID3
